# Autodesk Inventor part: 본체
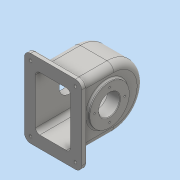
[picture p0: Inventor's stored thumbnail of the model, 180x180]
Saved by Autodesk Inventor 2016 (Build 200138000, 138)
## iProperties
Created: 2018-11
Part Number: 본체
Material: 일반
Document SubType Name: Modeling
Designer: user
Density: 1 g/cm^3
Appearance: 기본값
Mass: 404.408 g
Surface Area: 1182.6 cm^2
Volume: 404.408 cm^3
Author: user
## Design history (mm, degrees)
sketch "스케치1"
  geometry: L1 (-55, -75)-(55, -75); L2 (55, -75)-(55, 75); L3 (55, 75)-(-55, 75); L4 (-55, 75)-(-55, -75); L5 (-55, -75)-(55, 75); L6 (55, -75)-(-55, 75); 1 further point
  constraints: 12 end point, 2 midpoint, 2 parallel, 1 horizontal, 1 perpendicular
  dimensions: "d0" = 110 distance of L2.end L3.end; "d1" = 150 distance of L1.end L2.end
extrude "돌출1" new body sketch "스케치1" distance "d2" = 10; taper "d3" = 0 deg
sketch "스케치2"
  geometry: L1 (0, 75)-(0, -75) reference; L2 (78, -58)-(10, -58); L3 (78, 58)-(10, 58); L4 (10, 75)-(10, -75) reference; L5 (10, -58)-(10, 58); L6 (10, -75)-(10, 75) reference; L7 (0, -75)-(0, 75) reference; A1 r 58 centre (78, 0) between (78, -58) and (78, 58); 4 further points
  constraints: 6 end point, 3 midpoint, 3 vertical alignment, 2 horizontal, 2 point on circle, 2 point on line, 1 centre point, 1 collinear, 1 horizontal alignment
  dimensions: "d4" = 116 diameter of A1; "d5" = 78 distance from line of L1 A1.centre; "d8" = 116 distance between parallel lines of L3 L2
extrude "돌출2" join sketch "스케치2" stored distance "d6" = 77; taper "d7" = 0 deg
feature "쉘1" dims "d9" = 6, "d10" = 10, "d11" = 5
sketch "스케치3"
  geometry: L1 (-75, 0)-(75, 0) reference; C1 r 38 at (0, 65); 2 further points
  constraints: 1 centre point, 1 midpoint, 1 vertical alignment
  dimensions: "d12" = 76 diameter of C1; "d13" = 65 distance from line of L1 C1.centre
extrude "돌출3" join sketch "스케치3" distance "d14" = 10; taper "d15" = 0 deg
sketch "스케치4"
  geometry: L1 (-75, 0)-(75, 0) reference; C1 r 38 at (0, 65); 2 further points
  constraints: 1 centre point, 1 midpoint, 1 vertical alignment
  dimensions: "d16" = 76 diameter of C1; "d17" = 65 distance from line of L1 C1.centre
extrude "돌출4" join sketch "스케치4" distance "d18" = 5; taper "d19" = 0 deg
sketch "스케치5"
  geometry: L1 (19.5, 93)-(19.5, 65); L2 (43.5, 27)-(43.5, 103) reference; L3 (19.5, 93)-(33.5, 104.747); L4 (33.5, 78)-(33.5, 130) reference; L5 (19.5, 65)-(33.5, 65); L6 (33.5, 65)-(33.5, 104.747); 2 further points
  constraints: 8 end point, 1 collinear, 1 horizontal, 1 horizontal alignment, 1 midpoint, 1 point on line, 1 vertical
  dimensions: "d20" = 28 distance of L1.start L1.end; "d21" = 50 deg angle of L1 L3; "d23" = 24 distance between parallel lines of L1 L2
revolve "회전1" sketch "스케치5" stored, may be unused: angle "d24" = 90 deg
sketch "스케치6"
  geometry: C1 r 38 at (0, 0) reference; C2 r 20 at (0, 0); 1 further point
  constraints: 1 centre point, 1 coincident
  dimensions: "d25" = 40 diameter of C2
extrude "돌출5" cut sketch "스케치6" stored distance "d26" = 5; taper "d27" = 0 deg
sketch "스케치7"
  geometry: L1 (-75, -65)-(75, -65) reference; C1 r 29 at (0, 0); C2 r 38 at (0, 0) reference; 3 further points
  constraints: 1 centre point, 1 concentric, 1 midpoint, 1 vertical alignment
  dimensions: "d28" = 58 diameter of C1; "d29" = 29 distance of point (0, 29) C1.centre
hole "구멍1" sketch "스케치7" at (0, 29) diameter "d30" = 3.242; stored, may be unused: countersink angle "d34" = 90 deg, drill point angle "d36" = 118 deg; dims "d31" = 8, "d32" = 4, "d33" = 2, "d35" = 10
node "작업 평면1"
sketch "스케치8"
  geometry: C1 r 6 at (0, 0); 1 further point
  constraints: 1 centre point, 1 coincident
  dimensions: "d41" = 12 diameter of C1
extrude "돌출6" join sketch "스케치8" stored distance "d42" = 5; taper "d43" = 5 deg
sketch "스케치9"
  geometry: 1 further point
hole "구멍2" sketch "스케치9" at (0, 0) diameter "d44" = 4.459; stored, may be unused: countersink angle "d48" = 90 deg, drill point angle "d50" = 118 deg; dims "d45" = 10, "d46" = 4, "d47" = 2, "d49" = 12.8
fillet "모깎기1" dims "d51" = 12
sketch "스케치10"
  geometry: C1 r 6 at (43, 63); A1 r 12 centre (43, 63) between (55, 63) and (43, 75) reference; 1 further point
  constraints: 1 centre point, 1 coincident
  dimensions: "d52" = 12 diameter of C1
extrude "돌출7" cut sketch "스케치10" distance "d53" = 4; taper "d54" = 0 deg
sketch "스케치11"
  geometry: C1 r 2.5 at (0, 0); C2 r 6 at (0, 0) reference; 1 further point
  constraints: 1 centre point, 1 concentric
  dimensions: "d55" = 5 diameter of C1
extrude "돌출8" cut sketch "스케치11" stored distance "d56" = 4; taper "d57" = 0 deg
fillet "모깎기2" dims "d64" = 13
fillet "모깎기3" dims "d65" = 8
fillet "모깎기4" dims "d66" = 3
fillet "모깎기5" dims "d67" = 3
chamfer "모따기1" distance "d68" = 1; stored, may be unused: second distance "d69" = 2, angle "d70" = 45 deg
sketch "스케치12"
  geometry: L1 (-17.5, -78)-(68.5, -78) reference; L2 (-13, 0)-(-13, -65) reference; 2 further points
  constraints: 1 other
  dimensions: "d71" = 40 distance from line of L1 point (25.5, -38); "d72" = 38.5 distance from line of L2 point (25.5, -38)
feature "엠보싱1" sketch "스케치12" dims "d0" = 110, "d1" = 150, "d4" = 116, "d5" = 78, "d8" = 116, "d73" = 0.5, "d74" = 0
sketch "스케치13" dims "d75" = 58
  geometry: C1 r 38 at (0, 0) reference; 3 further points
  constraints: 2 vertical alignment, 3 other
hole "구멍3" sketch "스케치13" at (0, 29) diameter "d76" = 3.242; stored, may be unused: countersink angle "d80" = 90 deg, drill point angle "d82" = 118 deg; dims "d77" = 8, "d78" = 4, "d79" = 2, "d81" = 10
node "솔리드1"
pattern_circular "원형 패턴1" dims angle "d38" = 360 deg
pattern_linear "직사각형 패턴1" dims "d60" = 86, "d63" = 126
pattern_circular "원형 패턴2" dims angle "d84" = 360 deg
other parameters: "d40" = 142
